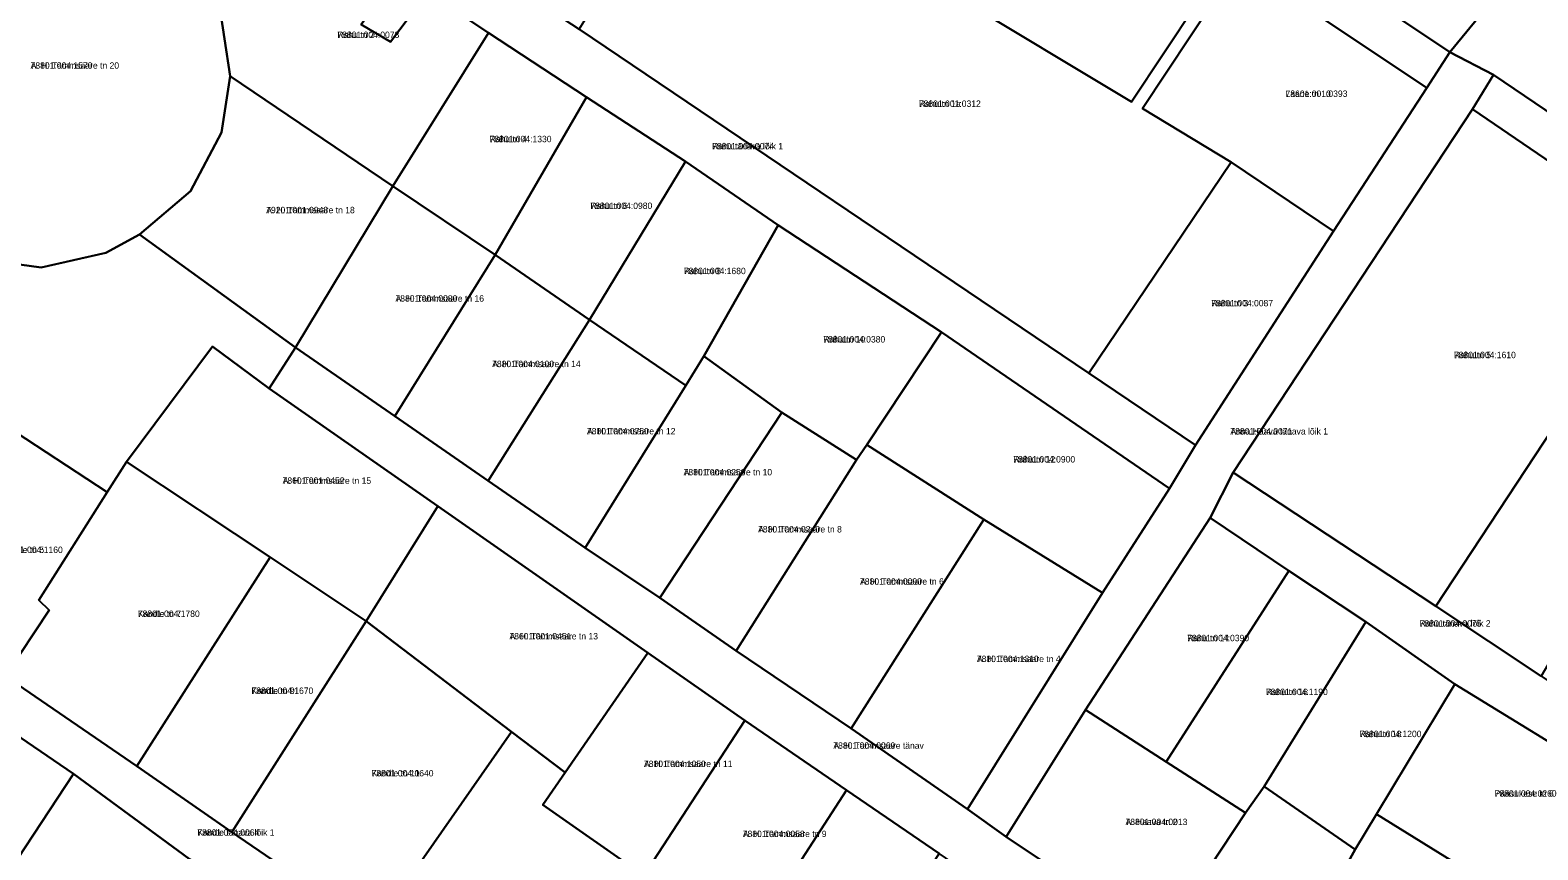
# Model space of a CAD drawing. Extents: x 587616 to 632239, y 6547421 to 6574977.
# Drawn here: x 620040.8 to 620393.8, y 6559726.2 to 6559918.3 of the extents above; entities that cross this region are included whole.
import ezdxf

# ---------------------------------------------------------------- set-up
doc = ezdxf.new("R2010")
doc.units = 0
for name, color, linetype in [('L_AADRESS', 7, 'Continuous'), ('PIIR', 7, 'Continuous'), ('TUNNUS', 7, 'Continuous')]:
    doc.layers.add(name, color=color, linetype=linetype)

msp = doc.modelspace()

# ---------------------------------------------------------------- linework, layer by layer
at = {"layer": 'PIIR'}
for points in [[(620348.76, 6559929.49), (620386.44, 6559974.98), (620408.55, 6559956.22), (620373.21, 6559913.1)], [(620094.2, 6559969.74), (620124.74, 6559948.92), (620136.62, 6559939.99), (620169.34, 6559918.51), (620288.7, 6559837.89), (620313.69, 6559821.01), (620307.59, 6559810.93), (620254.22, 6559847.49), (620215.97, 6559872.58), (620194.25, 6559887.53), (620171.05, 6559902.56), (620148.16, 6559917.63), (620133.91, 6559927.16), (620127.08, 6559931.73), (620087.58, 6559961.04)], [(620198.48, 6559962.68), (620217.97, 6559949.8), (620218.13, 6559950.04), (620257.08, 6559926.56), (620298.67, 6559901.48), (620321.42, 6559935.77), (620323.91, 6559934.1), (620301.24, 6559899.93), (620321.99, 6559887.37), (620288.7, 6559837.89), (620169.34, 6559918.51), (620170.96, 6559920.99)], [(620281.11, 6559962.78), (620321.42, 6559935.77), (620298.67, 6559901.48), (620257.08, 6559926.56)], [(620148.16, 6559917.63), (620125.73, 6559881.71), (620087.68, 6559907.51), (620084.98, 6559924.95), (620077.35, 6559938.38), (620087.58, 6559961.04), (620127.08, 6559931.73), (620118.35, 6559919.58), (620125.22, 6559915.55), (620133.91, 6559927.16)], [(620032.01, 6559955.16), (620039.68, 6559955.77), (620055.17, 6559953.83), (620065.76, 6559948.71), (620077.35, 6559938.38), (620084.98, 6559924.95), (620087.68, 6559907.51), (620085.58, 6559894.31), (620078.32, 6559880.52), (620066.43, 6559870.43), (620058.55, 6559866.11), (620043.39, 6559862.69), (620028.07, 6559864.77), (620014, 6559871.29), (620002.88, 6559882.36), (619995.19, 6559895.55), (619994.3, 6559911.15), (619997.65, 6559926.28), (620005.32, 6559939.44), (620017.45, 6559949.38)], [(620408.55, 6559956.22), (620411.47, 6559953.75), (620430.67, 6559937.46), (620397.98, 6559897.99), (620383.42, 6559907.82), (620373.21, 6559913.1)], [(620323.91, 6559934.1), (620367.85, 6559904.72), (620345.97, 6559871.14), (620321.99, 6559887.37), (620301.24, 6559899.93)], [(620127.08, 6559931.73), (620133.91, 6559927.16), (620125.22, 6559915.55), (620118.35, 6559919.58)], [(620148.16, 6559917.63), (620171.05, 6559902.56), (620149.72, 6559865.66), (620125.73, 6559881.71)], [(620383.42, 6559907.82), (620378.56, 6559899.73), (620322.47, 6559814.68), (620317.13, 6559803.99), (620287.95, 6559759.08), (620269.35, 6559729.3), (620260.26, 6559735.79), (620291.88, 6559786.47), (620307.59, 6559810.93), (620313.69, 6559821.01), (620345.97, 6559871.14), (620367.85, 6559904.72), (620373.21, 6559913.1)], [(620102.98, 6559843.93), (620066.43, 6559870.43), (620078.32, 6559880.52), (620085.58, 6559894.31), (620087.68, 6559907.51), (620125.73, 6559881.71)], [(620383.42, 6559907.82), (620397.98, 6559897.99), (620422.1, 6559881.65), (620446.22, 6559865.3), (620470.34, 6559848.96), (620502.21, 6559827.37), (620536.44, 6559804.18), (620595.04, 6559764.5), (620588.04, 6559752.82), (620585.78, 6559761.3), (620550.06, 6559781.64), (620515.94, 6559804.44), (620478.61, 6559832), (620471.18, 6559836.41), (620450.03, 6559851.28), (620425.9, 6559867.44), (620378.56, 6559899.73)], [(620149.72, 6559865.66), (620171.05, 6559902.56), (620194.25, 6559887.53), (620171.75, 6559850.4)], [(620322.47, 6559814.68), (620378.56, 6559899.73), (620425.9, 6559867.44), (620397.31, 6559824.93), (620369.98, 6559783.34)], [(620194.25, 6559887.53), (620215.97, 6559872.58), (620198.59, 6559841.9), (620194.32, 6559834.99), (620171.75, 6559850.4)], [(620321.99, 6559887.37), (620345.97, 6559871.14), (620313.69, 6559821.01), (620288.7, 6559837.89)], [(620126.22, 6559827.82), (620102.98, 6559843.93), (620125.73, 6559881.71), (620149.72, 6559865.66)], [(620198.59, 6559841.9), (620215.97, 6559872.58), (620254.22, 6559847.49), (620236.75, 6559821.11), (620234.28, 6559817.61), (620216.84, 6559828.66)], [(620126.22, 6559827.82), (620149.72, 6559865.66), (620171.75, 6559850.4), (620148.04, 6559812.66)], [(620148.04, 6559812.66), (620171.75, 6559850.4), (620194.32, 6559834.99), (620170.78, 6559797)], [(620236.75, 6559821.11), (620254.22, 6559847.49), (620307.59, 6559810.93), (620291.88, 6559786.47), (620264.08, 6559803.66)], [(620063.36, 6559817.12), (620083.49, 6559844.14), (620096.81, 6559834.31), (620136.28, 6559806.73), (620119.49, 6559779.84), (620096.98, 6559794.83)], [(620361.51, 6559665.07), (620355.38, 6559655.91), (620317.01, 6559681.71), (620288.71, 6559701.56), (620263.03, 6559719.01), (620253.65, 6559725.38), (620231.93, 6559740.23), (620208.19, 6559756.54), (620185.44, 6559772.38), (620136.28, 6559806.73), (620096.81, 6559834.31), (620102.98, 6559843.93), (620126.22, 6559827.82), (620148.04, 6559812.66), (620170.78, 6559797), (620188.22, 6559785.29), (620206.16, 6559772.9), (620233.07, 6559754.7), (620260.26, 6559735.79), (620269.35, 6559729.3), (620305.6, 6559705.03), (620328.59, 6559688.28)], [(620170.78, 6559797), (620194.32, 6559834.99), (620198.59, 6559841.9), (620216.84, 6559828.66), (620188.22, 6559785.29)], [(620188.22, 6559785.29), (620216.84, 6559828.66), (620234.28, 6559817.61), (620206.16, 6559772.9)], [(620035.06, 6559825.64), (620058.83, 6559810.02), (620042.84, 6559784.77), (620045.25, 6559782.41), (620035.07, 6559766.91), (620009.07, 6559784.65), (620034.58, 6559824.89)], [(620369.98, 6559783.34), (620397.31, 6559824.93), (620420.56, 6559809.23), (620417.66, 6559804.87), (620409.32, 6559791.93), (620394.59, 6559766.95)], [(620264.08, 6559803.66), (620233.07, 6559754.7), (620206.16, 6559772.9), (620234.28, 6559817.61), (620236.75, 6559821.11)], [(619959.37, 6559818.56), (619987.62, 6559799.28), (620009.07, 6559784.65), (620035.07, 6559766.91), (620065.76, 6559745.85), (620088.05, 6559730.37), (620121.32, 6559707.65), (620151.91, 6559686.72), (620205.8, 6559651.21), (620199.23, 6559640.57), (620175.85, 6559656.75), (620147.25, 6559676.56), (620127.57, 6559690.19), (620106.06, 6559705.08), (620086.33, 6559718.74), (620078.08, 6559724.17), (620050.93, 6559744.03), (620009.2, 6559772.57), (619953.1, 6559808.8)], [(620065.76, 6559745.85), (620035.07, 6559766.91), (620045.25, 6559782.41), (620042.84, 6559784.77), (620058.83, 6559810.02), (620063.36, 6559817.12), (620096.98, 6559794.83)], [(620322.47, 6559814.68), (620369.98, 6559783.34), (620394.59, 6559766.95), (620417.02, 6559752.04), (620411.28, 6559742.42), (620374.38, 6559765.08), (620353.52, 6559779.68), (620335.49, 6559791.61), (620317.13, 6559803.99)], [(620119.49, 6559779.84), (620136.28, 6559806.73), (620185.44, 6559772.38), (620166.06, 6559744.34), (620153.48, 6559753.92)], [(620233.07, 6559754.7), (620264.08, 6559803.66), (620291.88, 6559786.47), (620260.26, 6559735.79)], [(620306.78, 6559746.87), (620287.95, 6559759.08), (620317.13, 6559803.99), (620335.49, 6559791.61)], [(619966.79, 6559799.99), (620009.2, 6559772.57), (619983.04, 6559736.39), (619977.14, 6559727.57), (620006.53, 6559707.94), (620026.61, 6559707.09), (620050.93, 6559744.03), (620078.08, 6559724.17), (620048.49, 6559676.66), (620034.32, 6559598.44), (619968.93, 6559610.71), (619964.54, 6559708.8)], [(620088.05, 6559730.37), (620065.76, 6559745.85), (620096.98, 6559794.83), (620119.49, 6559779.84)], [(620325.36, 6559734.89), (620306.78, 6559746.87), (620335.49, 6559791.61), (620353.52, 6559779.68), (620329.78, 6559741.11)], [(620088.05, 6559730.37), (620119.49, 6559779.84), (620153.48, 6559753.92), (620121.32, 6559707.65)], [(620356.06, 6559734.59), (620351.09, 6559726.32), (620329.78, 6559741.11), (620353.52, 6559779.68), (620374.38, 6559765.08)], [(619983.04, 6559736.39), (620009.2, 6559772.57), (620050.93, 6559744.03), (620026.61, 6559707.09)], [(620160.86, 6559736.81), (620185.44, 6559772.38), (620208.19, 6559756.54), (620184.52, 6559720.21)], [(620374.38, 6559765.08), (620411.28, 6559742.42), (620391.94, 6559712.34), (620356.06, 6559734.59)], [(620287.95, 6559759.08), (620306.78, 6559746.87), (620325.36, 6559734.89), (620305.6, 6559705.03), (620269.35, 6559729.3)], [(620153.48, 6559753.92), (620166.06, 6559744.34), (620160.86, 6559736.81), (620184.52, 6559720.21), (620183.41, 6559718.41), (620175.88, 6559723.4), (620151.91, 6559686.72), (620121.32, 6559707.65)], [(620183.41, 6559718.41), (620184.52, 6559720.21), (620208.19, 6559756.54), (620231.93, 6559740.23), (620206.71, 6559701.25)], [(620206.71, 6559701.25), (620231.93, 6559740.23), (620253.65, 6559725.38), (620227.88, 6559686.07)], [(620305.6, 6559705.03), (620325.36, 6559734.89), (620329.78, 6559741.11), (620351.09, 6559726.32), (620342.99, 6559711.9), (620328.59, 6559688.28)], [(620351.09, 6559726.32), (620356.06, 6559734.59), (620391.94, 6559712.34), (620377.3, 6559689.63), (620342.99, 6559711.9)]]:
    msp.add_lwpolyline(points, close=True, dxfattribs=at)
for points in [[(620348.76, 6559929.49), (620373.21, 6559913.1), (620367.85, 6559904.72), (620323.91, 6559934.1)], [(620028.07, 6559864.77), (620043.39, 6559862.69), (620058.55, 6559866.11), (620066.43, 6559870.43), (620102.98, 6559843.93), (620096.81, 6559834.31), (620083.49, 6559844.14), (620063.36, 6559817.12), (620058.83, 6559810.02), (620035.06, 6559825.64)]]:
    msp.add_lwpolyline(points, dxfattribs=at)

# ---------------------------------------------------------------- texts
at = {"layer": 'L_AADRESS'}
for s, p in [('Rahu tn 2', (620112.75, 6559916.43)), ('A. H. Tammsaare tn 20', (620040.91, 6559909.23)), ('Rahu tn 1a', (620248.9, 6559900.29)), ('Laane tn 10', (620334.75, 6559902.62)), ('Rahu tn 4', (620148.39, 6559892.01)), ('Rahu tänava lõik 1', (620200.49, 6559890.33)), ('A. H. Tammsaare tn 18', (620096.08, 6559875.37)), ('Rahu tn 6', (620171.98, 6559876.37)), ('Rahu tn 8', (620193.86, 6559861.1)), ('A. H. Tammsaare tn 16', (620126.35, 6559854.66)), ('Rahu tn 3', (620317.34, 6559853.56)), ('Rahu tn 10', (620226.52, 6559845.09)), ('Rahu tn 5', (620374.18, 6559841.42)), ('A. H. Tammsaare tn 14', (620148.98, 6559839.32)), ('A. H. Tammsaare tn 12', (620171.18, 6559823.57)), ('Anna Haava tänava lõik 1', (620321.84, 6559823.54)), ('Rahu tn 12', (620270.99, 6559816.98)), ('A. H. Tammsaare tn 15', (620099.92, 6559811.99)), ('A. H. Tammsaare tn 10', (620193.81, 6559813.96)), ('A. H. Tammsaare tn 8', (620211.25, 6559800.59)), ('Kandle tn 5', (620033.95, 6559795.79)), ('A. H. Tammsaare tn 6', (620235.12, 6559788.37)), ('Kandle tn 7', (620066.02, 6559780.81)), ('Rahu tänava lõik 2', (620366.15, 6559778.55)), ('A. H. Tammsaare tn 13', (620153.03, 6559775.54)), ('Rahu tn 14', (620311.72, 6559775.12)), ('A. H. Tammsaare tn 4', (620262.48, 6559770.23)), ('Kandle tn 9', (620092.62, 6559762.78)), ('Rahu tn 16', (620330.15, 6559762.5)), ('Rahu tn 18', (620352.08, 6559752.65)), ('A. H. Tammsaare tänav', (620228.88, 6559749.92)), ('A. H. Tammsaare tn 11', (620184.52, 6559745.64)), ('Kandle tn 11', (620120.76, 6559743.45)), ('Pääsukese tn 6', (620383.72, 6559738.71)), ('A. Haava tn 2', (620297.28, 6559732.05)), ('Kandle tänava lõik 1', (620079.97, 6559729.57)), ('A. H. Tammsaare tn 9', (620207.67, 6559729.24))]:
    msp.add_text(s, height=1.5, dxfattribs=at).set_placement(p)
at = {"layer": 'TUNNUS'}
for s, p in [('78801:004:0078', (620112.75, 6559916.43)), ('78801:004:1570', (620040.91, 6559909.23)), ('78601:001:0312', (620248.9, 6559900.29)), ('78601:001:0393', (620334.75, 6559902.62)), ('78801:004:1330', (620148.39, 6559892.01)), ('78801:004:0074', (620200.49, 6559890.33)), ('79201:001:0948', (620096.08, 6559875.37)), ('78801:004:0980', (620171.98, 6559876.37)), ('78801:004:1680', (620193.86, 6559861.1)), ('78801:004:0080', (620126.35, 6559854.66)), ('78801:004:0087', (620317.34, 6559853.56)), ('78801:004:0380', (620226.52, 6559845.09)), ('78801:004:1610', (620374.18, 6559841.42)), ('78801:004:0100', (620148.98, 6559839.32)), ('78801:004:0750', (620171.18, 6559823.57)), ('78801:004:0071', (620321.84, 6559823.54)), ('78801:004:0900', (620270.99, 6559816.98)), ('78601:001:0452', (620099.92, 6559811.99)), ('78801:004:0250', (620193.81, 6559813.96)), ('78801:004:0240', (620211.25, 6559800.59)), ('78801:004:1160', (620033.95, 6559795.79)), ('78801:004:0090', (620235.12, 6559788.37)), ('78801:004:1780', (620066.02, 6559780.81)), ('78801:004:0075', (620366.15, 6559778.55)), ('78601:001:0451', (620153.03, 6559775.54)), ('78801:004:0390', (620311.72, 6559775.12)), ('78801:004:1310', (620262.48, 6559770.23)), ('78801:004:1670', (620092.62, 6559762.78)), ('78801:004:1190', (620330.15, 6559762.5)), ('78801:004:1200', (620352.08, 6559752.65)), ('78801:004:0069', (620228.88, 6559749.92)), ('78801:004:1050', (620184.52, 6559745.64)), ('78801:004:0640', (620120.76, 6559743.45)), ('78801:004:0260', (620383.72, 6559738.71)), ('78801:004:0013', (620297.28, 6559732.05)), ('78801:004:0064', (620079.97, 6559729.57)), ('78801:004:0058', (620207.67, 6559729.24))]:
    msp.add_text(s, height=1.5, dxfattribs=at).set_placement(p)

doc.saveas('drawing.dxf')
